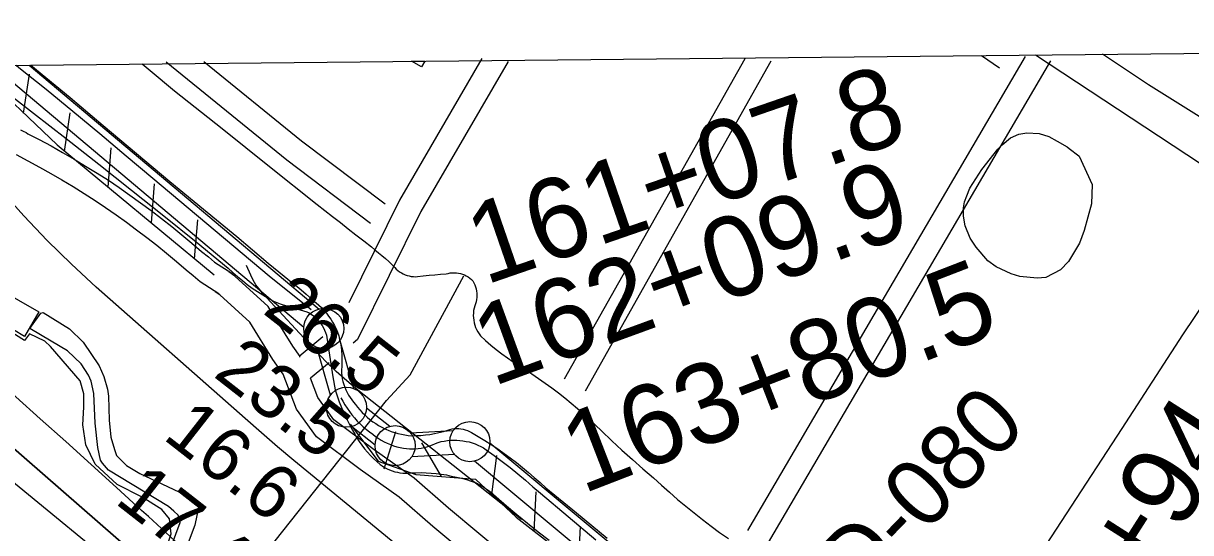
# Model space of a CAD drawing. Extents: x 3625074 to 3663148, y 511451 to 537151.
# Drawn here: x 3629186 to 3630641, y 534460 to 535095 of the extents above; entities that cross this region are included whole.
import ezdxf

# ---------------------------------------------------------------- set-up
doc = ezdxf.new("R2010")
doc.units = 0
for name, color, linetype in [('V-BLDG-OTLN', 7, 'Continuous'), ('V-CHAN-DOCK', 7, 'Continuous'), ('V-FLOD-BASE', 7, 'Continuous'), ('V-GRID-FRAM', 7, 'Continuous'), ('V-LEVE-TOET', 7, 'Continuous'), ('V-RIVR-EDGE', 7, 'Continuous'), ('V-RIVR-JETY', 7, 'Continuous'), ('V-RIVR-RANG', 7, 'Continuous'), ('V-RIVR-RANG-IDEN', 7, 'Continuous'), ('V-ROAD-CNTR', 7, 'Continuous'), ('V-RRAP-FSHR', 7, 'Continuous'), ('V-SITE-VEGE', 7, 'Continuous'), ('V-SURV-IDEN', 7, 'Continuous'), ('V-SURV-LINE', 7, 'Continuous'), ('V-TOPO-DPTH', 7, 'Continuous'), ('V-TOPO-MAJR', 7, 'Continuous'), ('V-TOPO-MINR', 7, 'Continuous'), ('V-TOPO-SHOR', 7, 'Continuous'), ('V-UTIL-LINE', 7, 'Continuous')]:
    doc.layers.add(name, color=color, linetype=linetype)

msp = doc.modelspace()

# ---------------------------------------------------------------- linework, layer by layer
at = {"layer": 'V-BLDG-OTLN'}
for p, q in [((3629670.3, 535047.6), (3629686.7, 535047.7)), ((3629682.9, 535040.7), (3629670.3, 535047.6)), ((3629686.7, 535047.7), (3629682.9, 535040.7))]:
    msp.add_line(p, q, dxfattribs=at)
at = {"layer": 'V-CHAN-DOCK'}
for points in [[(3629132, 534777.3), (3629205.9, 534735.4)], [(3629205.9, 534735.4), (3629188, 534704.5), (3629132.4, 534737.8)]]:
    msp.add_lwpolyline(points, dxfattribs=at)
at = {"layer": 'V-FLOD-BASE'}
for p, q in [((3629347.9, 534901.8), (3629492.9, 534780.1)), ((3629492.9, 534780.1), (3629545.3, 534738))]:
    msp.add_line(p, q, dxfattribs=at)
for points in [[(3629177.5, 535042.6), (3629181, 535039.8), (3629214.7, 535012.5), (3629248.2, 534985.1), (3629281.6, 534957.5), (3629314.8, 534929.7), (3629347.9, 534901.8)], [(3629582.1, 534628.2), (3629584.5, 534623.7), (3629587.1, 534619.3), (3629589.9, 534615), (3629592.9, 534610.8), (3629596, 534606.8), (3629599.3, 534602.9), (3629602.7, 534599.1), (3629606.3, 534595.5), (3629610.1, 534592), (3629614, 534588.7), (3629618, 534585.6), (3629622.1, 534582.6), (3629625.5, 534580), (3629628.9, 534577.6), (3629632.5, 534575.3), (3629636.3, 534573.3), (3629640.1, 534571.4), (3629644, 534569.8), (3629648, 534568.4), (3629652, 534567.1), (3629656.1, 534566.1), (3629660.3, 534565.3), (3629664, 534564.8), (3629667.6, 534564.5), (3629671.3, 534564.4), (3629675, 534564.5), (3629678.7, 534564.8), (3629682.3, 534565.3), (3629686, 534566.1), (3629689.5, 534567.1), (3629693, 534568.2), (3629696.5, 534569.6), (3629700, 534571.1), (3629703.6, 534572.4), (3629707.4, 534573.4), (3629711.1, 534574.2), (3629715, 534574.8), (3629718.8, 534575.2), (3629722.7, 534575.3), (3629726.6, 534575.2), (3629730.4, 534574.8), (3629734.3, 534574.4), (3629738.2, 534573.8), (3629742, 534573), (3629745.8, 534571.9), (3629749.5, 534570.7), (3629753.1, 534569.2), (3629756.6, 534567.5), (3629760.1, 534565.6), (3629763.4, 534563.4), (3629773.4, 534556.1), (3629783.3, 534548.6), (3629793.1, 534541), (3629802.7, 534533.2), (3629812.3, 534525.3), (3629821.7, 534517.3), (3629831, 534509.1), (3629865.5, 534480.1), (3629900, 534451.2)]]:
    msp.add_lwpolyline(points, dxfattribs=at)
at = {"layer": 'V-GRID-FRAM'}
msp.add_lwpolyline([(3629129.4, 535042.1), (3660791.6, 535359.9), (3660982, 517178), (3629304, 516860), (3629129.4, 535042.1)], dxfattribs=at)
at = {"layer": 'V-LEVE-TOET'}
for points in [[(3629334.5, 535044.2), (3629344.5, 535035.9), (3629374.8, 535010.5), (3629434.1, 534963.5), (3629493.4, 534916.4), (3629552.5, 534869.1), (3629562.2, 534861.5), (3629571.9, 534853.9), (3629581.6, 534846.4), (3629591.3, 534838.8), (3629601, 534831.2), (3629610.7, 534823.6), (3629620.3, 534816.1), (3629624.6, 534812.5), (3629629, 534808.9), (3629633.3, 534805.3), (3629637.7, 534801.7), (3629642, 534798.1), (3629645.7, 534794.2), (3629649.4, 534790.3), (3629651.3, 534788.4), (3629653.2, 534786.7), (3629655.4, 534785.1), (3629657.6, 534783.7), (3629659.9, 534782.5), (3629662.3, 534781.4), (3629664.8, 534780.5), (3629667.4, 534779.9), (3629669.9, 534779.4), (3629672.6, 534779.1), (3629675.2, 534779), (3629677.8, 534779.1), (3629684.9, 534780), (3629692.1, 534780.8), (3629699.2, 534781.5), (3629706.4, 534782), (3629713.6, 534782.4), (3629716.1, 534783.1), (3629718.6, 534783.6), (3629721.2, 534783.8), (3629723.8, 534783.9), (3629726.3, 534783.7), (3629728.9, 534783.4), (3629731.4, 534782.8)], [(3629129.5, 535037), (3629131.7, 535035.2), (3629165.3, 535008.9), (3629199, 534982.7), (3629239.8, 534951), (3629280.5, 534919.1), (3629321.1, 534887), (3629361.5, 534854.7), (3629401.8, 534822.3), (3629441.9, 534789.6)], [(3629441.9, 534789.6), (3629447.6, 534784.3), (3629453.4, 534779.2), (3629459.4, 534774.2), (3629465.5, 534769.4), (3629471.8, 534764.8), (3629478.2, 534760.4), (3629484.8, 534756.2), (3629491.4, 534752.2), (3629498.2, 534748.4), (3629506.4, 534745.3), (3629514.6, 534742.5), (3629523, 534739.9), (3629531.4, 534737.5), (3629539.9, 534735.4), (3629542.7, 534733.8), (3629545.4, 534732.1), (3629548, 534730.2), (3629550.5, 534728.1), (3629552.8, 534725.8), (3629555, 534723.3), (3629557, 534720.8), (3629558.8, 534718.1), (3629560.4, 534715.2), (3629561.8, 534712.3), (3629563.1, 534709.3), (3629564.1, 534706.2), (3629564.9, 534703), (3629567.1, 534686.7), (3629569.6, 534670.4), (3629572.3, 534654.1), (3629575.2, 534637.9), (3629577.6, 534630.5), (3629580.3, 534623.1), (3629583.2, 534615.8), (3629586.3, 534608.6), (3629589.6, 534601.6), (3629593.1, 534594.6), (3629596.9, 534587.7), (3629599.5, 534582.8), (3629602.2, 534578.1), (3629605.2, 534573.4), (3629608.4, 534568.9), (3629611.7, 534564.6), (3629615.3, 534560.3), (3629619, 534556.3), (3629622.9, 534552.4), (3629626.9, 534548.6), (3629631.2, 534545.1), (3629633.9, 534543.1), (3629636.8, 534541.3), (3629639.8, 534539.7), (3629642.9, 534538.3), (3629646, 534537), (3629649.3, 534536), (3629652.6, 534535.2), (3629655.9, 534534.6), (3629659.3, 534534.2), (3629662.7, 534534.1), (3629666.1, 534534.1), (3629669.4, 534534.4), (3629675.8, 534534.7), (3629682.1, 534534.8), (3629688.5, 534534.7), (3629694.8, 534534.3), (3629701.1, 534533.7), (3629707.4, 534532.9), (3629713.7, 534531.9), (3629719.9, 534530.6), (3629726.2, 534529.3), (3629732.5, 534527.8), (3629738.7, 534526.1), (3629744.8, 534524.2), (3629750.9, 534522), (3629754.7, 534520), (3629758.5, 534517.9), (3629762.2, 534515.6), (3629765.8, 534513.1), (3629769.2, 534510.5), (3629772.5, 534507.7), (3629775.7, 534504.8), (3629788.6, 534493.6), (3629801.7, 534482.5), (3629814.9, 534471.7), (3629828.3, 534461), (3629841.8, 534450.5)], [(3629731.4, 534782.8), (3629733.9, 534782.1), (3629736.3, 534781.1), (3629738.6, 534780), (3629740.8, 534778.7), (3629742.9, 534777.2), (3629744.9, 534775.5), (3629746.7, 534773.7), (3629748, 534771.4), (3629749.2, 534768.9), (3629750.1, 534766.4), (3629750.8, 534763.8), (3629751.3, 534761.1), (3629751.7, 534758.5), (3629751.7, 534755.8), (3629751.6, 534753.1), (3629751.3, 534750.4), (3629750.7, 534747.8), (3629750, 534745.2), (3629749, 534742.6), (3629748.3, 534739.7), (3629747.7, 534736.7), (3629747.4, 534733.7), (3629747.3, 534730.6), (3629747.4, 534727.6), (3629747.8, 534724.6), (3629748.4, 534721.6), (3629749.2, 534718.6), (3629750.2, 534715.7), (3629751.4, 534713), (3629752.9, 534710.3), (3629754.5, 534707.7), (3629756.3, 534705.2), (3629762.7, 534699.4), (3629769.2, 534693.7), (3629775.9, 534688.2), (3629782.8, 534682.9), (3629789.8, 534677.8), (3629796.9, 534672.9), (3629804.1, 534668.1), (3629811.5, 534663.6), (3629820.1, 534658), (3629828.6, 534652.3), (3629837, 534646.5), (3629845.3, 534640.4), (3629853.5, 534634.2), (3629861.5, 534627.9), (3629869.4, 534621.4), (3629877.2, 534614.8), (3629884.9, 534608), (3629892.4, 534601), (3629899.8, 534593.9), (3629907.1, 534586.7), (3629919.8, 534574.6), (3629932.6, 534562.7), (3629945.6, 534551), (3629958.8, 534539.5), (3629972.1, 534528.2), (3629981.9, 534519.2), (3629991.8, 534510.3), (3630001.9, 534501.5), (3630012.1, 534492.9), (3630022.5, 534484.5), (3630032.9, 534476.3), (3630043.6, 534468.2), (3630054.3, 534460.3), (3630065.2, 534452.6)]]:
    msp.add_lwpolyline(points, dxfattribs=at)
at = {"layer": 'V-RIVR-EDGE'}
msp.add_lwpolyline([(3629300.9, 534292.2), (3629319.3, 534311.8), (3629338.5, 534360.8), (3629370.6, 534458.7), (3629368.8, 534477.1), (3629359, 534488.8), (3629334.5, 534504.2), (3629303.3, 534520.2), (3629275.8, 534545.4), (3629264.2, 534569.3), (3629260.6, 534594.4), (3629261.9, 534616.5), (3629261.9, 534633), (3629257.1, 534649), (3629220.4, 534691.9), (3629213.1, 534698.7), (3629194.1, 534707.9), (3629187.9, 534699.4), (3629132.4, 534733.9)], dxfattribs=at)
at = {"layer": 'V-RIVR-JETY'}
for points in [[(3629354.7, 534400.1), (3629382, 534472.8), (3629382, 534475.8), (3629379.6, 534481.7), (3629374.2, 534486.8), (3629367.3, 534492.6), (3629292.7, 534537.9), (3629284.9, 534546.7), (3629282.6, 534550.3), (3629279.2, 534566), (3629276.1, 534596.6), (3629274.4, 534633.3), (3629271, 534648.9), (3629267.8, 534656.3), (3629258.5, 534670.3), (3629241.6, 534686.4), (3629221, 534698.6), (3629194.4, 534714.4), (3629194.4, 534714.4), (3629208.1, 534733.5), (3629211.1, 534734.3)], [(3629211.1, 534734.3), (3629243.8, 534714.2), (3629260.8, 534697.4), (3629281, 534667.9), (3629286.6, 534654.6), (3629291.5, 534639), (3629292.5, 534630), (3629293.3, 534600.1), (3629295.3, 534579.1), (3629300.2, 534563.5), (3629302.7, 534556.1), (3629315, 534543.7), (3629331.7, 534533.6), (3629401.5, 534501), (3629404.8, 534491.3), (3629400.1, 534469.5), (3629333.6, 534292.4)]]:
    msp.add_lwpolyline(points, dxfattribs=at)
at = {"layer": 'V-ROAD-CNTR'}
for points in [[(3629195.7, 535042.8), (3629244.8, 535002.4), (3629286, 534967.3), (3629327.5, 534932.5), (3629369, 534897.8), (3629410.8, 534863.3), (3629452.7, 534829.1)], [(3629619.3, 534845.3), (3629514.7, 534924.1), (3629364.4, 535046.2)], [(3629637.4, 534869.2), (3629533.1, 534947.8), (3629411.4, 535046.7)], [(3629758.1, 535051), (3629655.4, 534874.5), (3629592, 534746.3)], [(3629790.6, 535047.2), (3629681.8, 534860.3), (3629602.9, 534700.6), (3629597.6, 534696.2)], [(3630085.6, 535050.6), (3629860.7, 534651.1)], [(3630118.2, 535047.4), (3629886.9, 534636.4)], [(3630089.4, 534462.8), (3630435.6, 535053.6)], [(3630115.3, 534447.7), (3630467, 535047.8)], [(3630448.2, 535055.4), (3630772.8, 534841.6)], [(3630794.8, 534889.3), (3630589, 535018.1), (3630531.7, 535056.2)], [(3629182.9, 534961.8), (3629186.4, 534960.3), (3629189.9, 534958.6), (3629192.1, 534957.2), (3629206.3, 534949.8), (3629220.9, 534941.9), (3629235.4, 534933.7), (3629249.8, 534925.4), (3629264.1, 534916.9), (3629278.3, 534908.2), (3629292.4, 534899.2), (3629306, 534890), (3629319.3, 534880.7), (3629332.6, 534871.2), (3629345.6, 534861.5), (3629358.6, 534851.6), (3629371.4, 534841.5), (3629384.1, 534831.3), (3629396.6, 534820.9), (3629408.7, 534810.4), (3629417.1, 534803.6), (3629424.8, 534797.1), (3629446.3, 534783.3)], [(3629177.3, 534931.1), (3629192.2, 534923.3), (3629206.5, 534915.6), (3629220.6, 534907.7), (3629234.6, 534899.6), (3629248.6, 534891.2), (3629262.3, 534882.7), (3629275.9, 534874.1), (3629289, 534865.3), (3629302, 534856.2), (3629314.9, 534846.9), (3629327.6, 534837.5), (3629340.2, 534827.9), (3629352.7, 534818.1), (3629365, 534808.1), (3629377.2, 534798), (3629389.4, 534787.4), (3629397.9, 534780.5), (3629406.9, 534772.9), (3629430.1, 534758.1)], [(3630735.6, 534865), (3630691.9, 534796.7), (3630631.5, 534706.5), (3630555.7, 534589.9), (3630417.1, 534377)], [(3629452.7, 534829.1), (3629472.1, 534812.4), (3629491.7, 534795.9), (3629511.4, 534779.6), (3629520.7, 534772.3), (3629529.9, 534764.9), (3629539, 534757.3), (3629547.8, 534749.5)], [(3629559.8, 534703.9), (3629530.3, 534679.6), (3629531.6, 534679.5), (3629522.5, 534692.3), (3629491.8, 534741.9), (3629449.9, 534779.8), (3629442.5, 534785)], [(3629510.3, 534657.7), (3629497.5, 534675.7), (3629468.6, 534722.5), (3629431.2, 534756.3), (3629425.4, 534760.3)], [(3629547.8, 534749.5), (3629551.4, 534746.6), (3629554.8, 534743.6), (3629558, 534740.4), (3629561.1, 534737), (3629564.1, 534733.5), (3629566.9, 534729.9), (3629569.5, 534726.1), (3629571.9, 534722.2), (3629574.1, 534718.3), (3629576.2, 534714.2), (3629578.1, 534710), (3629579.5, 534705.4), (3629580.7, 534700.8), (3629581.7, 534696.1), (3629582.5, 534691.4), (3629583.1, 534686.6), (3629583.5, 534681.8), (3629583.6, 534677), (3629583.6, 534672.3), (3629583.3, 534667.5), (3629582.9, 534662.7), (3629583, 534659.1), (3629583.4, 534655.4), (3629584, 534651.8), (3629584.8, 534648.3), (3629585.8, 534644.8), (3629587, 534641.3), (3629588.4, 534637.9), (3629589.9, 534634.7), (3629591.7, 534631.5), (3629593.6, 534628.4), (3629595.7, 534625.4), (3629598, 534622.5), (3629600.4, 534619.8), (3629603, 534616.3), (3629605.8, 534613), (3629608.8, 534609.8), (3629611.9, 534606.7), (3629615.1, 534603.8), (3629618.5, 534601), (3629622, 534598.3), (3629625.6, 534595.9), (3629629.3, 534593.6), (3629633.1, 534591.5), (3629637, 534589.5), (3629641, 534587.8), (3629645.1, 534586.2), (3629649.2, 534584.8), (3629653.4, 534583.6), (3629657.7, 534582.6), (3629662, 534581.8), (3629666.3, 534581.2), (3629670.7, 534580.8), (3629676.3, 534580.9), (3629682, 534581.2), (3629687.7, 534581.7), (3629693.3, 534582.5), (3629698.9, 534583.5), (3629704.5, 534584.7), (3629710, 534586.1), (3629715.4, 534587.7), (3629718.1, 534588.6)], [(3629567.8, 534671.6), (3629544.4, 534652.4)], [(3630434.1, 533741.8), (3630390.7, 533784.3), (3630342.7, 533836.4), (3630300, 533891.2), (3630282, 533914.9), (3630262.3, 533950.5), (3630241.9, 533992.6), (3630223, 534024.4), (3630196.2, 534066.3), (3630170.4, 534095.9), (3630101.9, 534155.5), (3629993.4, 534245), (3629904, 534307.4), (3629811.6, 534372.1), (3629696.9, 534467.8), (3629655, 534504.3), (3629606.1, 534538.8), (3629551.7, 534579.3), (3629527, 534614), (3629510.3, 534657.7)], [(3630674.8, 533567.1), (3630628.1, 533613.2), (3630529.8, 533703.7), (3630470.1, 533748.5), (3630412.3, 533805.2), (3630365.6, 533855.8), (3630323.8, 533909.5), (3630307.2, 533931.3), (3630288.9, 533964.3), (3630268.3, 534006.8), (3630248.5, 534040.1), (3630220.3, 534084.3), (3630191.7, 534117.2), (3630121.3, 534178.4), (3630011.6, 534268.9), (3629921.2, 534332), (3629829.8, 534396), (3629716.3, 534490.6), (3629673.6, 534527.9), (3629623.7, 534563.1), (3629573.4, 534600.5), (3629553.6, 534628.3), (3629544.4, 534652.4)], [(3629718.1, 534588.6), (3629720.8, 534589.2), (3629723.5, 534589.6), (3629726.3, 534589.8), (3629729.1, 534589.8), (3629731.9, 534589.5), (3629734.6, 534589), (3629737.3, 534588.2), (3629740, 534587.3), (3629742.5, 534586.1), (3629744.9, 534584.7)], [(3629744.9, 534584.7), (3629753.3, 534579.9), (3629761.5, 534574.9), (3629769.6, 534569.7), (3629777.7, 534564.3), (3629785.6, 534558.8), (3629793.4, 534553.1), (3629801.1, 534547.3), (3629808.6, 534541.3), (3629816, 534535.1), (3629823.3, 534528.8), (3629830.5, 534522.4), (3629837.5, 534515.8), (3629875.9, 534484.5), (3629914.1, 534453.1)]]:
    msp.add_lwpolyline(points, dxfattribs=at)
at = {"layer": 'V-RRAP-FSHR'}
for p, q in [((3629186.8, 534982.9), (3629193.9, 535031.2)), ((3629237.7, 534934.8), (3629244.8, 534983.2)), ((3629292.2, 534890.7), (3629296.1, 534939.4)), ((3629346, 534846.1), (3629350, 534894.7)), ((3629399.9, 534801.4), (3629403.9, 534850)), ((3629636, 534539.7), (3629650.9, 534586.2)), ((3629707.8, 534529.9), (3629683.1, 534572.1)), ((3629770.2, 534507.6), (3629776.8, 534556)), ((3629823.2, 534462), (3629825.7, 534510.7)), ((3629878.5, 534419), (3629880.9, 534467.8))]:
    msp.add_line(p, q, dxfattribs=at)
for points in [[(3629129.5, 535037), (3629228.5, 534943.5), (3629424.1, 534781.3)], [(3629593.7, 534595.4), (3629628.9, 534549.1), (3629675.7, 534532.6), (3629749.9, 534526.5), (3629800.6, 534479.5), (3629966.7, 534350.4), (3630089.2, 534242), (3630199.3, 534163.2), (3630240.7, 534124.3), (3630335.5, 533982.1), (3630401.2, 533866.3), (3630489.7, 533770.2), (3630626, 533630.9), (3630830.3, 533447.2)], [(3629593.7, 534595.4), (3629628.9, 534549.1), (3629675.7, 534532.6), (3629749.9, 534526.5), (3629800.6, 534479.5), (3629966.7, 534350.4), (3630089.2, 534242), (3630199.3, 534163.2), (3630240.7, 534124.3), (3630335.5, 533982.1), (3630401.2, 533866.3), (3630489.7, 533770.2), (3630626, 533630.9), (3630821.3, 533451.9)]]:
    msp.add_lwpolyline(points, dxfattribs=at)
at = {"layer": 'V-SITE-VEGE'}
msp.add_lwpolyline([(3630490.1, 534938.9), (3630501.9, 534929.4), (3630502.5, 534929.1), (3630518.6, 534894), (3630518, 534869.6), (3630508.8, 534836.4), (3630502.7, 534820.8), (3630489.3, 534797.8), (3630479.4, 534787.6), (3630460.9, 534778), (3630450.3, 534777.3), (3630428.6, 534779.2), (3630417.8, 534782.5), (3630399.1, 534791.2), (3630388.8, 534798.8), (3630374, 534815.6), (3630366.8, 534826.8), (3630360.5, 534842.4), (3630358.2, 534854.3), (3630358.3, 534864.7), (3630359.7, 534872.2), (3630362.4, 534879.6), (3630366.2, 534889.2), (3630381.1, 534912.7), (3630401.1, 534938.1), (3630406.5, 534943.3), (3630417, 534951.9), (3630427.2, 534956.6), (3630437.1, 534958.1), (3630452.5, 534957.3), (3630464.6, 534953.8), (3630475.2, 534948), (3630487.6, 534941)], close=True, dxfattribs=at)
at = {"layer": 'V-SURV-LINE'}
for points in [[(3629193.6, 535042.8), (3629555.3, 534738.7)], [(3629536, 534715.7), (3629147.5, 535042.3)], [(3629580.9, 534699.3), (3629598.1, 534639.6)], [(3629569.2, 534631.3), (3629552.1, 534691)], [(3629614.1, 534615.7), (3629643.4, 534592.6)], [(3629624.8, 534569), (3629595.6, 534592.1)], [(3629668.9, 534584.5), (3629722.3, 534587.3)], [(3629768, 534572.1), (3630285.5, 534140.3)], [(3629723.9, 534557.4), (3629670.5, 534554.5)], [(3630266.3, 534117.2), (3629748.8, 534549.1)]]:
    msp.add_lwpolyline(points, dxfattribs=at)
for centre in [(3629560.9, 534714.4), (3629589.2, 534616.3), (3629649.8, 534568.4), (3629743, 534573.4)]:
    msp.add_circle(centre, 25, dxfattribs=at)
at = {"layer": 'V-TOPO-DPTH'}
msp.add_lwpolyline([(3629135, 534458), (3629133.7, 534600.4), (3629167.8, 534570.8), (3629347.5, 534414), (3629358.4, 534404.5), (3629369.1, 534394.8), (3629379.8, 534385), (3629390.4, 534375.1), (3629607.9, 534169), (3629723.1, 534059.3), (3629837.9, 533949.1), (3629952, 533838.2), (3630065.8, 533727), (3630250.2, 533545.6), (3630271.3, 533524.6), (3630292.3, 533503.5), (3630313, 533482.1), (3630333.6, 533460.6), (3630453, 533334.8), (3630491.8, 533291.8), (3630529, 533247.5), (3630564, 533201.5), (3630597.5, 533154.3), (3630641.7, 533088.6)], dxfattribs=at)
at = {"layer": 'V-TOPO-MAJR'}
msp.add_lwpolyline([(3629807.3, 534476.2), (3629603.3, 534637.6), (3629589.6, 534649), (3629576.3, 534660.8), (3629563.6, 534673.2), (3629551.3, 534686), (3629484.6, 534758.6), (3629480.3, 534763.7), (3629476.4, 534769), (3629473, 534774.7), (3629470, 534780.7), (3629464.4, 534792.9)], dxfattribs=at)
at = {"layer": 'V-TOPO-MINR'}
for points in [[(3630507.6, 533770.6), (3630493.5, 533781), (3630486.4, 533786.2), (3630479.4, 533791.4), (3630472.5, 533796.7), (3630465.6, 533802), (3630109, 534078.5), (3630006.9, 534158.4), (3629905.1, 534238.9), (3629804.1, 534320.2), (3629703.5, 534402.1), (3629544.3, 534532.9), (3629523.7, 534549.9), (3629503.3, 534567.1), (3629483.1, 534584.6), (3629463, 534602.1), (3629277.4, 534766), (3629246.3, 534794.7), (3629216, 534824.1), (3629187.1, 534854.8), (3629158.9, 534886.4), (3629140.5, 534907.9), (3629130.6, 534920.2)], [(3630783.4, 533068.1), (3630356.9, 533487.5), (3630336.6, 533507.4), (3630316.3, 533527.3), (3630296.1, 533547.3), (3630275.8, 533567.2), (3630255.5, 533587.1), (3630235.2, 533607), (3630214.9, 533626.9), (3630194.6, 533646.8), (3629449.4, 534378.7), (3629423, 534404.4), (3629396.4, 534429.8), (3629369.4, 534455), (3629342.3, 534480), (3629333.9, 534487.7), (3629302.4, 534516.3), (3629270.8, 534544.9), (3629239.2, 534573.4), (3629207.5, 534601.9), (3629177, 534629.3), (3629136.9, 534667), (3629133, 534670.9)], [(3630641.7, 533088.6), (3630597.5, 533154.3), (3630564, 533201.5), (3630529, 533247.5), (3630491.8, 533291.8), (3630453, 533334.8), (3630333.6, 533460.6), (3630313, 533482.1), (3630292.3, 533503.5), (3630271.3, 533524.6), (3630250.2, 533545.6), (3630065.8, 533727), (3629952, 533838.2), (3629837.9, 533949.1), (3629723.1, 534059.3), (3629607.9, 534169), (3629390.4, 534375.1), (3629379.8, 534385), (3629369.1, 534394.8), (3629358.4, 534404.5), (3629347.5, 534414), (3629167.8, 534570.8), (3629133.7, 534600.4)], [(3630365.6, 533373.6), (3630342.7, 533399.5), (3630319.4, 533425), (3630285.1, 533461.3), (3630276.5, 533470.3), (3630267.9, 533479.2), (3630259.1, 533488), (3630250.4, 533496.7), (3629464.2, 534270.3), (3629446.1, 534288), (3629427.8, 534305.6), (3629409.4, 534323.1), (3629390.9, 534340.4), (3629356.2, 534372.5), (3629354.9, 534373.7), (3629352.3, 534375.9), (3629351, 534377), (3629134.1, 534555.1)]]:
    msp.add_lwpolyline(points, dxfattribs=at)
at = {"layer": 'V-TOPO-SHOR'}
msp.add_line((3630380.7, 535054.7), (3630403.2, 535039.1), dxfattribs=at)
at = {"layer": 'V-UTIL-LINE'}
msp.add_lwpolyline([(3629321.6, 534224.8), (3629638.9, 534624.7), (3629668.7, 534656.5), (3629735.3, 534779.9)], dxfattribs=at)

# ---------------------------------------------------------------- texts
at = {"layer": 'V-RIVR-RANG'}
for s, p in [('26.5', (3629483.1, 534734.6)), ('23.5', (3629421.7, 534655.7)), ('16.6', (3629358.8, 534577.9)), ('17.4', (3629298.8, 534497.8))]:
    msp.add_text(s, height=67, rotation=321.9683, dxfattribs=at).set_placement(p)
at = {"layer": 'V-RIVR-RANG-IDEN'}
msp.add_text('D-080', height=83, rotation=46.0273, dxfattribs=at).set_placement((3630229.3, 534374.5))
at = {"layer": 'V-SURV-IDEN'}
for s, rotation, p in [('161+07.8', 19.05, (3629761.9, 534768.3)), ('162+09.9', 20.0484, (3629771.3, 534641.8)), ('163+80.5', 21.163, (3629883.3, 534507.9)), ('174+01.2', 58.1467, (3630642.6, 534227.1)), ('170+94.6', 57.4851, (3630465.8, 534205.8))]:
    msp.add_text(s, height=100, rotation=rotation, dxfattribs=at).set_placement(p)

doc.saveas('drawing.dxf')
